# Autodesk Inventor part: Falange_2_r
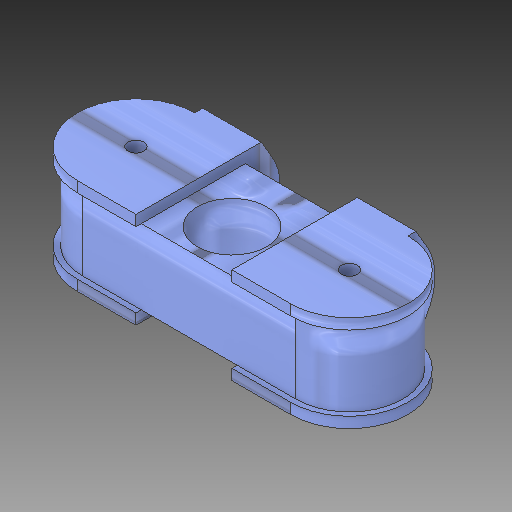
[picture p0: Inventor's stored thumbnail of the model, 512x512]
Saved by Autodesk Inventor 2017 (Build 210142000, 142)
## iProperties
Created: 2017-05
Part Number: Falange_2_r
Material: Generic
Document SubType Name: Modeling
Designer: alez_
Density: 1 g/cm^3
Appearance: Default
Author: alez_
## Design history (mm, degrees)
derived "Falange_2.ipt" dims "d0" = 11
feature "Solid1::Falange_2.ipt" dims "d0" = 11
tag "TaggingFeature1"
body "Solid1"
